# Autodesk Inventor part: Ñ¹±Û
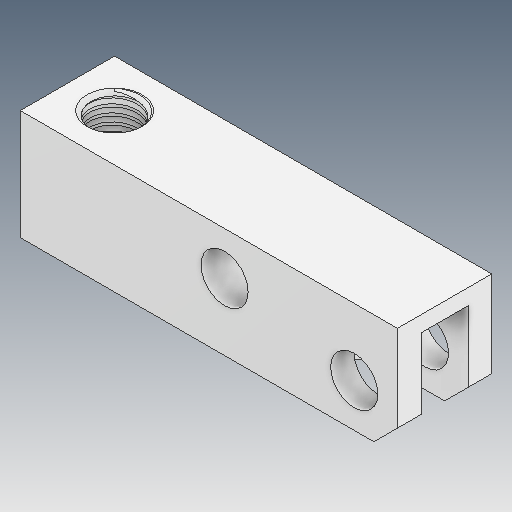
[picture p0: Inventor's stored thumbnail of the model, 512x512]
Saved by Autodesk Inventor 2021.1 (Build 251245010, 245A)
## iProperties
Created: 2021-06
Part Number: Ñ¹±Û
Material: Ogólny
Document SubType Name: Modeling
Designer: user
Density: 1 g/cm^3
Appearance: Domyślna
Author: user
Revision Number: ÈÎºÎ
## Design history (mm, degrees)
feature "ÇÐ³ý-É¨Ãè1"
node "Bryła1"
